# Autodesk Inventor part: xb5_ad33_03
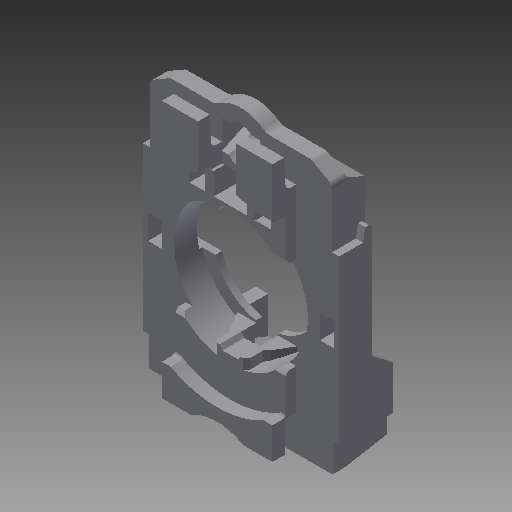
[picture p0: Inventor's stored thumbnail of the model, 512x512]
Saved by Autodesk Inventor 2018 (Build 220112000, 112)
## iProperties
Company: TraceParts S.A.
Created: 2018-05
Part Number: xb5_ad33_03
Checked By: TraceParts S.A.
Material: Generic
Catalog Web Link: www.traceparts.com
Document SubType Name: Modeling
Designer: TraceParts
Density: 1 g/cm^3
Appearance: Default
Author: TraceParts
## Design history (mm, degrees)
feature "xb5_ad33_03.ipt"
body "Solid1"
